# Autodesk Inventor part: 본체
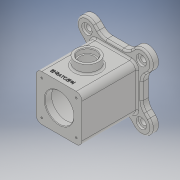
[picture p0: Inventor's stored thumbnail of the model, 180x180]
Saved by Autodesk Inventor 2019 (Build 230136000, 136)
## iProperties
Created: 2021-01
Part Number: 본체
Material: 일반
Document SubType Name: Modeling
Designer: 3dpro6
Density: 1 g/cm^3
Appearance: 기본값
Mass: 385.772 g
Surface Area: 854.467 cm^2
Volume: 385.772 cm^3
Author: 3dpro6
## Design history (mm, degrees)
sketch "스케치1"
  geometry: L1 (22.544, 48)-(-22.544, 48); L2 (-48, 22.544)-(-48, -22.544); L3 (-22.544, -48)-(22.544, -48); L4 (48, -22.544)-(48, 22.544); L5 (47.376, -47.376)-(0, 0); L6 (0, 0)-(-47.376, -47.376); L7 (47.376, 47.376)-(0, 0); L8 (-47.376, 47.376)-(0, 0); L9 (-34.648, -60.104)-(-22.544, -48); L10 (-60.104, -34.648)-(-48, -22.544); L11 (34.648, -60.104)-(22.544, -48); L12 (60.104, -34.648)-(48, -22.544); L13 (60.104, 34.648)-(48, 22.544); L14 (34.648, 60.104)-(22.544, 48); L15 (-34.648, 60.104)-(-22.544, 48); L16 (-60.104, 34.648)-(-48, 22.544); C1 r 25 at (0, 0); A1 r 18 centre (47.376, -47.376) between (34.648, -60.104) and (60.104, -34.648); A2 r 18 centre (-47.376, -47.376) between (-60.104, -34.648) and (-34.648, -60.104); A3 r 18 centre (47.376, 47.376) between (60.104, 34.648) and (34.648, 60.104); A4 r 18 centre (-47.376, 47.376) between (-34.648, 60.104) and (-60.104, 34.648); A5 r 67 centre (0, 0) between (47.376, -47.376) and (-47.376, -47.376); 9 further points
  constraints: 32 end point, 20 point on circle, 10 parallel, 9 point on line, 8 tangent, 6 centre point, 2 coincident, 2 perpendicular, 1 horizontal, 1 horizontal alignment, 1 vertical alignment
  dimensions: "d2" = 36 diameter of A1; "d3" = 36 diameter of A2; "d4" = 36 diameter of A3; "d5" = 36 diameter of A4; "d7" = 134 diameter of A5; "d8" = 96 distance between parallel lines of L1 L3; "d9" = 96 distance between parallel lines of L2 L4; "d10" = 48 distance from line of L4 point (0, 0); "d11" = 48 distance from line of L3 point (0, 0); "d12" = 50 diameter of C1; "d56" = 90 deg angle of L6 L5; "d57" = 90 deg angle of L8 L6
extrude "돌출1" new body sketch "스케치1" distance "d13" = 12; taper "d14" = 0 deg
sketch "스케치2"
  geometry: L1 (-40, -40)-(40, -40); L2 (40, -40)-(40, 40); L3 (40, 40)-(-40, 40); L4 (-40, 40)-(-40, -40); L5 (-40, -40)-(40, 40); L6 (40, -40)-(-40, 40); 1 further point
  constraints: 12 end point, 2 midpoint, 2 parallel, 1 horizontal, 1 perpendicular
  dimensions: "d15" = 80 distance of L3.end L2.end; "d16" = 80 distance of L2.end L1.end
extrude "돌출2" join sketch "스케치2" distance "d17" = 96; taper "d18" = 0 deg
sketch "스케치3"
  geometry: L1 (22.544, -48)-(-22.544, -48) reference; L2 (48, 22.544)-(48, -22.544) reference; L3 (-22.544, 48)-(22.544, 48) reference; L4 (-48, -22.544)-(-48, 22.544) reference; L5 (-30, -30)-(30, -30); L6 (30, -30)-(30, 30); L7 (30, 30)-(-30, 30); L8 (-30, 30)-(-30, -30); L9 (-30, -30)-(30, 30); L10 (30, -30)-(-30, 30); L11 (-60.104, -34.648)-(-48, -22.544) reference; L12 (-22.544, -48)-(-34.648, -60.104) reference; L13 (34.648, -60.104)-(22.544, -48) reference; L14 (48, -22.544)-(60.104, -34.648) reference; L15 (60.104, 34.648)-(48, 22.544) reference; L16 (22.544, 48)-(34.648, 60.104) reference; L17 (-34.648, 60.104)-(-22.544, 48) reference; L18 (-48, 22.544)-(-60.104, 34.648) reference; C1 r 25 at (0, 0) reference; A1 r 18 centre (-47.376, -47.376) between (-60.104, -34.648) and (-34.648, -60.104) reference; A2 r 18 centre (47.376, -47.376) between (34.648, -60.104) and (60.104, -34.648) reference; A3 r 18 centre (47.376, 47.376) between (60.104, 34.648) and (34.648, 60.104) reference; A4 r 18 centre (-47.376, 47.376) between (-34.648, 60.104) and (-60.104, 34.648) reference; 4 further points
  constraints: 12 end point, 3 coincident, 2 midpoint, 2 parallel, 1 horizontal, 1 perpendicular
  dimensions: "d19" = 60 distance of L7.end L6.end; "d20" = 60 distance of L6.end L5.end
hole "구멍1" sketch "스케치3" at (30, -30), (-30, 30), (-30, -30), (30, 30) diameter "d21" = 3.242; stored, may be unused: countersink angle "d25" = 90 deg, drill point angle "d27" = 118 deg; dims "d22" = 8, "d23" = 4, "d24" = 2, "d26" = 10
sketch "스케치4"
  geometry: L1 (-30, 30)-(30, 30); L2 (30, 30)-(30, -30); L3 (30, -30)-(-30, -30); L4 (-30, -30)-(-30, 30); L5 (-30, 30)-(30, -30); L6 (30, 30)-(-30, -30); C1 r 1.621 at (-30, 30) reference; 5 further points
  constraints: 12 end point, 4 coincident, 2 midpoint, 2 parallel, 1 horizontal, 1 perpendicular
  dimensions: "d28" = 60 distance of L2.end L3.end; "d29" = 60 distance of L1.end L2.end
hole "구멍2" sketch "스케치4" at (30, 30), (30, -30), (-30, -30), (-30, 30) diameter "d30" = 3.242; stored, may be unused: countersink angle "d34" = 90 deg, drill point angle "d36" = 118 deg; dims "d31" = 8, "d32" = 4, "d33" = 2, "d35" = 10
sketch "스케치5"
  geometry: C1 r 25 at (0, 0); 1 further point
  constraints: 1 centre point, 1 coincident
  dimensions: "d37" = 50 diameter of C1
extrude "돌출3" cut sketch "스케치5" distance "d38" = 96; taper "d39" = 0 deg
sketch "스케치6"
  geometry: L1 (0, 133.167)-(0, -26.833); L2 (0, 12)-(35, 12); L3 (0, 96)-(35, 96); L4 (25, 0)-(-25, 0) reference; L5 (-25, 108)-(25, 108) reference; L6 (25, 0)-(25, 108) reference; L7 (35, 96)-(35, 12); L8 (0, 96)-(0, 12); 1 further point
  constraints: 10 end point, 3 point on line, 2 horizontal, 1 collinear, 1 vertical
  dimensions: "d40" = 160 distance of L1.start L1.end; "d41" = 35 distance of L2.start L2.end; "d42" = 35 distance of L3.start L3.end; "d43" = 12 distance between parallel lines of L2 L4; "d44" = 12 distance between parallel lines of L3 L5
revolve "회전1" sketch "스케치6" stored, may be unused: angle "d45" = 90 deg
sketch "스케치7"
  geometry: A1 r 18 centre (47.376, -47.376) between (34.648, -60.104) and (60.104, -34.648) reference; 4 further points
  constraints: 1 coincident
hole "구멍3" sketch "스케치7" at (47.376, -47.376) diameter "d46" = 10; stored, may be unused: countersink angle "d50" = 90 deg, drill point angle "d52" = 0 deg; dims "d47" = 8, "d48" = 18, "d49" = 4, "d51" = 10
sketch "스케치8"
  geometry: L1 (17.456, -12)-(62.544, -12) reference; C1 r 20 at (40, 47); 3 further points
  constraints: 1 centre point, 1 midpoint, 1 vertical alignment
  dimensions: "d58" = 40 diameter of C1; "d59" = 59 distance from line of L1 C1.centre
extrude "돌출4" join sketch "스케치8" distance "d60" = 15; taper "d61" = 0 deg
sketch "스케치9"
  geometry: C1 r 20 at (0, 0) reference; 2 further points
  constraints: 1 coincident
hole "구멍4" sketch "스케치9" at (0, 0) diameter "d62" = 25; stored, may be unused: countersink angle "d66" = 90 deg, drill point angle "d68" = 0 deg; dims "d63" = 6, "d64" = 30, "d65" = 8, "d67" = 25
sketch "스케치10"
  geometry: L1 (0, 96)-(80, 96) reference; L2 (17.456, -12)-(62.544, -12) reference; 4 further points
  constraints: 1 point on line, 1 vertical alignment, 1 other
  dimensions: "d69" = 10 distance from line of L1 point (43.542, 86)
feature "엠보싱1" sketch "스케치10" dims "d4" = 36, "d17" = 96, "d70" = 0.5, "d71" = 0
fillet "모깎기1" dims "d72" = 10
fillet "모깎기3" dims "d74" = 20
fillet "모깎기4" dims "d75" = 3
chamfer "모따기1" distance "d76" = 1; stored, may be unused: second distance "d77" = 2, angle "d78" = 45 deg
fillet "모깎기5" dims "d79" = 3
node "솔리드1"
pattern_circular "원형 패턴1" dims angle "d54" = 360 deg
node "투영된 루프1"
